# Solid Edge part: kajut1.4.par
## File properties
Author: Mac
Template: Normal.par
Last saved by: Mac
Revision: 16
Application: Solid Edge
Density: 1300,000 kg/m^3
Accuracy: 0,990
Material: Epoxy, cast rigid
Face Style: White
Fill Style: ANSI34(Plastic)
Virtual Style: Shiny resin yellow
Coef. of Thermal Exp: 5.9e-05
Thermal Conductivity: 2.1
Specific Heat: 0.0
Modulus of Elasticity: 3102640650.0
Poission's Ratio: 0.37
Yield Stress: 65500191.5
Ultimate Stress: 0.0
Elongation: 0.0
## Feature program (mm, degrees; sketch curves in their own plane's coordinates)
sketch for "unnamed Protrusion 1" plane through (0, 0, 0) normal (0, 0, 1) x-axis (1, 0, 0)
extrude "unnamed Protrusion 1" add to key point along +normal
replace surface "unnamed ReplaceSurface 1"
sketch for "unnamed Cutout 1" plane through (17.2231, 15.1706, 0) normal (0, 0, -1) x-axis (1, 0, 0)
  line (59.2433, 13.6622) -> (-66.6267, 13.6622)
  line (-66.6267, 50.0572) -> (-66.6267, 13.6622)
  line (-66.6267, 50.0572) -> (59.2433, 50.0572)
  line (59.2433, 50.0572) -> (59.2433, 13.6622)
extrude "unnamed Cutout 1" cut through along -normal
replace surface "unnamed ReplaceSurface 2"
sketch for "unnamed Cutout 2" plane through (16.7161, 1.5084, 17.0568) normal (0, -1, 0) x-axis (1, 0, 0)
  bspline degree 3 poles (9.663, 14.79) (2.5101, 14.9839) (-7.8188, 15.3708) (-21.8608, 14.1482) (-31.0602, 14.1732) (-36.3205, 11.4707) (-51.3807, 10.4837) (-63.2728, 9.3157) (-76.3437, 8.8273) knots 0 0.2257 0.3868 0.4835 0.539 0.5875 1 multiplicities 4 1 1 1 1 1 4
  line (-76.3437, 8.8273) -> (-76.3437, 24.7599)
  line (-76.3437, 24.7599) -> (9.663, 24.7599)
  line (9.663, 24.7599) -> (9.663, 14.79)
extrude "unnamed Cutout 2" cut through along -normal
fillet "Round_3" radius 2
fillet "Round_4" radius 6
fillet "Round_5" radius 2
lofted cutout "unnamed LoftedCutout 1"
sketch for "ExtrudedProtrusion_4" plane through (-14.725, 13.9689, 23.98) normal (0, 0, 1) x-axis (1, 0, 0)
  line (5.4244, -12.4605) -> (-7.7485, -12.4605)
  line (-7.7485, 12.6611) -> (-7.7485, -12.4605)
  line (-7.7485, 12.6611) -> (5.4244, 11.5251)
  line (5.4244, 11.5251) -> (5.4244, -12.4605)
extrude "ExtrudedProtrusion_4" add finite 3 along +normal
sketch for "ExtrudedCutout_6" plane through (0, 31.8282, 0) normal (0, -1, 0) x-axis (1, 0, 0)
  line (50.9356, 3.4307) -> (-32.1242, 3.4307)
  line (50.9356, 3.4307) -> (29.8402, 16.8869)
  line (29.8402, 16.8869) -> (11.2912, 16.8869)
extrude "ExtrudedCutout_6" cut along +normal  Profile_Plane1_Distance = 31.8282 mm
sketch for "unnamed Cutout 3" plane through (65.5056, 0, 0) normal (1, 0, 0) x-axis (0, 1, 0)
  line (1.5043, 3.4307) -> (24.5141, 3.4307)
  line (24.5141, 16.8869) -> (24.5141, 3.4307)
  line (1.5051, 16.8869) -> (24.5141, 16.8869)
  bspline degree 3 poles (1.5043, 3.4307) (1.5046, 7.7872) (1.5048, 12.364) (1.5051, 16.8869) knots 0 1 multiplicities 4 4
extrude "unnamed Cutout 3" cut along +normal
lofted cutout "unnamed LoftedCutout 2"
sketch for "ExtrudedCutout_9" plane through (-32.1251, 15.8889, 13.7207) normal (-1, 0, 0) x-axis (0, -1, 0)
extrude "ExtrudedCutout_9" cut finite 33.2398 along -normal
body pattern "unnamed BodyPattern 1"
pattern "unnamed Pattern 1"
sketch for "unnamed Cutout 4" plane through (-27.2968, 1.5084, 23.78) normal (0, 0, 1) x-axis (0, -1, 0)
  line (0.9627, 19.288) -> (0.9627, 1.6734)
  line (0.9627, 1.6734) -> (4.9627, 1.6734)
  line (4.9627, 19.288) -> (4.9627, 1.6734)
  line (0.9627, 19.288) -> (4.9627, 19.288)
extrude "unnamed Cutout 4" cut along +normal
sketch for "unnamed Protrusion 2" plane through (-8.7893, -12.7105, 25.3849) normal (0.939693, 0, -0.34202) x-axis (0, 1, 0)
  arc centre (1.7521, 7.2455) radius 2 from (3.7521, 7.2455) to (1.7521, 9.2455) ccw
  line (3.7521, 7.2455) -> (3.7521, 1.675)
  line (3.7521, 1.675) -> (-0.2479, 1.675)
  line (-0.2479, 7.2455) -> (-0.2479, 1.675)
  arc centre (1.7521, 7.2455) radius 2 from (-0.2479, 7.2455) to (1.7521, 9.2455) cw
extrude "unnamed Protrusion 2" add through along +normal
sketch for "unnamed Protrusion 3" plane through (-10.8012, 1.5084, 23.98) normal (0, 0, 1) x-axis (1, 0, 0)
  line (11.6904, -14.4667) -> (0.584, -14.4667)
  line (0.584, -10.4667) -> (0.584, -14.4667)
  line (11.6904, -10.4668) -> (0.584, -10.4667)
  line (11.6904, -10.4668) -> (11.6904, -14.4667)
extrude "unnamed Protrusion 3" add along +normal
sketch for "unnamed Protrusion 4" plane through (-15.4114, -13.3019, 27.9786) normal (-0.140003, 0, 0.990151) x-axis (0, -1, 0)
  line (7.1676, -7.1324) -> (10.173, -7.1324)
  bspline degree 3 poles (8.1689, 14.8756) (8.3705, 13.0412) (8.5582, 11.2063) (8.8135, 8.4565) (8.893, 7.5407) (9.0467, 5.7061) (9.1218, 4.787) (9.2739, 2.9584) (9.351, 2.0478) (9.4699, 0.6916) (9.5094, 0.2413) (9.5955, -0.6559) (9.6413, -1.1031) (9.7808, -2.4439) (9.8766, -3.3377) (9.9607, -4.2354) (10.0508, -5.1968) (10.1165, -6.1637) (10.173, -7.1324) knots 0 0.222 0.333 0.444 0.555 0.6105 0.666 0.777 1 multiplicities 4 2 2 2 2 2 2 3 4
  line (-2.1162, 19.1742) -> (-2.1162, 16.0491)
  bspline degree 3 poles (5.3665, 12.8768) (4.9125, 13.1058) (4.4832, 13.3319) (3.6377, 13.7653) (3.2128, 13.9785) (2.3797, 14.374) (1.9605, 14.5622) (1.5389, 14.7404) (0.3553, 15.2407) (-0.8641, 15.6707) (-2.1162, 16.0491) knots 0 0.1546 0.3191 0.4836 1 multiplicities 4 2 2 3 4
  bspline degree 3 poles (7.1676, -7.1324) (7.0849, -5.4182) (6.8925, -3.6731) (6.7039, -1.8603) (6.657, -1.4102) (6.6104, -0.9551) (6.5215, -0.0291) (6.4813, 0.4295) (6.3619, 1.7919) (6.2845, 2.7068) (6.1319, 4.5412) (6.0568, 5.4597) (5.904, 7.2843) (5.8253, 8.1911) (5.6243, 10.3551) (5.499, 11.6154) (5.3665, 12.8768) knots 0 0.316 0.3795 0.443 0.5699 0.6969 0.8238 1 multiplicities 4 3 2 2 2 2 2 4
extrude "unnamed Protrusion 4" add through along -normal
replace surface "unnamed ReplaceSurface 3"
thinwall "Thinwall_5"  Thickness = 0.1 mm
sketch for "ExtrudedCutout_13" plane through (0, 0, 0) normal (0, -1, 0) x-axis (1, 0, 0)
  bspline degree 3 poles (11.2912, 16.2869) (3.5878, 16.3363) (-2.7766, 16.1026) (-8.2178, 15.3761) (-13.0948, 14.7248) (-17.2301, 13.6777) (-20.9403, 12.0868) knots 0 0.381 1 multiplicities 4 3 4
  bspline degree 3 poles (-6.0657, 4.0307) (-9.9941, 6.9536) (-14.9512, 9.6357) (-20.9403, 12.0868) knots 0 1 multiplicities 4 4
  line (48.8793, 4.0307) -> (-6.0657, 4.0307)
  line (48.8793, 4.0307) -> (29.6651, 16.2869)
  line (29.6651, 16.2869) -> (11.2912, 16.2869)
extrude "ExtrudedCutout_13" cut finite 127.1905 symmetric
sketch for "unnamed Cutout 5" #1 plane through (0, 0, 0) normal (1, 0, 0) x-axis (0, 1, 0)
  line (24.0141, 16.3869) -> (24.0141, 4.0307)
  line (24.0141, 4.0307) -> (2.1084, 4.0307)
  line (2.1084, 16.3869) -> (2.1084, 4.0307)
  line (2.1084, 16.3869) -> (24.0141, 16.3869)
sketch for "unnamed Cutout 5" #2 plane through (0, 0, 0) normal (1, 0, 0) x-axis (0, 1, 0)
  line (0.9084, 16.2869) -> (-20.8974, 16.2869)
  line (-20.8974, 16.2869) -> (-20.8974, 4.0307)
  line (-20.8974, 4.0307) -> (0.9084, 4.0307)
  line (0.9084, 16.2869) -> (0.9084, 4.0307)
extrude "unnamed Cutout 5" cut through along +normal
sketch for "unnamed Cutout 6" plane through (-6.9179, -10.9584, 30.5264) normal (-0.939693, 0, 0.34202) x-axis (0, -1, 0)
extrude "unnamed Cutout 6" cut through along -normal
Other named dimensions: "OffsetSurface_1": Distance = 0.08 mm | "OffsetSurface_2": Distance = 0.08 mm | "ExtrudedSurface_1": FiniteDepth = 33.8703 mm | "KeypointCurve_12": EndDerivMagnitude = -6.9482 mm
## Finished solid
Body 1: sheet body, 1 face, 4 edges, 4 vertices.
  Faces by surface: spline 1
  Edges by curve: spline 4
Body 2: sheet body, 5 faces, 28 edges, 24 vertices.
  Faces by surface: offset 3, blend 1, plane 1
  Edges by curve: curve on surface 17, intersection 6, line 4, circle 1
Body 3: sheet body, 1 face, 4 edges, 4 vertices.
  Faces by surface: plane 1
  Edges by curve: line 4
Body 4: sheet body, 1 face, 5 edges, 5 vertices.
  Faces by surface: offset 1
  Edges by curve: curve on surface 5
Body 5: sheet body, 1 face, 5 edges, 5 vertices.
  Faces by surface: offset 1
  Edges by curve: curve on surface 5
Body 6: sheet body, 1 face, 6 edges, 6 vertices.
  Faces by surface: spline 1
  Edges by curve: spline 6
Body 7: solid body, 158 faces, 462 edges, 305 vertices.
  Faces by surface: plane 82, offset 30, blend 16, spline 15, swept 12, cylinder 3
  Edges by curve: intersection 246, line 169, curve on surface 23, circle 16, spline 6, ellipse 2
Body 8: sheet body, 1 face, 4 edges, 4 vertices.
  Faces by surface: spline 1
  Edges by curve: spline 4
Bounding box of the edges (mm; curved faces can reach further): 97.800 x 62.270 x 34.175, from (-32.1319, -27.3865, -0.0609) to (65.6678, 34.883, 34.1136).
Cylindrical faces by radius (mm): R0.75 x1, R1.9 x1, R2 x1
Planar faces by outward normal: +x 5, +y 11, +z 15, -x 5, -y 11, -z 19, oblique 16
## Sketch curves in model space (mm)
spline (-0.0911, -12.9481, 30.1448) -> (-1.1705, -15.655, 29.9922) -> (-2.6614, -18.6684, 29.7814)
spline (-0.8642, -12.9584, 23.98) -> (-1.775, -16.0938, 23.98) -> (-2.8285, -18.7696, 23.98)
line (-32.1251, 29.2689, 15.3989) -> (-32.1251, 34.1731, 15.3989)
line (-32.1251, 34.1731, 15.3989) -> (-32.1251, 34.1731, 31.184)
line (-32.1251, 34.1731, 31.184) -> (-32.1251, -2.4744, 31.184)
line (-32.1251, -2.4744, 31.184) -> (-32.1251, -2.4744, 23.78)
line (-32.1251, -2.4744, 23.78) -> (-32.1251, 1.5084, 23.78)
line (-32.1251, 26.6168, 23.78) -> (-32.1251, 1.5084, 23.78)
line (-32.1251, 26.6168, 23.78) -> (-32.1251, 26.8456, 27.4401)
line (-32.1251, 26.926, 27.4401) -> (-32.1251, 26.8456, 27.4401)
arc centre (-32.1251, 26.926, 25.6295) radius 1.8106 from (-32.1251, 26.926, 27.4401) through (-32.1251, 28.1727, 26.9424) to (-32.1251, 28.7341, 25.7231)
line (-32.1251, 28.7341, 25.7231) -> (-32.1251, 29.2689, 15.3989)
arc centre (-22.4735, 26.4777, 26.3356) radius 1.8156 from (-22.4735, 28.2859, 26.4992) through (-22.4735, 27.6621, 27.7117) to (-22.4735, 26.4777, 28.1512)
line (-22.4735, 26.4777, 28.1512) -> (-22.4735, 26.4401, 28.1512)
spline (-22.4735, 26.4401, 28.1512) -> (-22.4735, 26.3035, 25.9656) -> (-22.4735, 26.1677, 23.78)
line (-22.4735, 26.1677, 23.78) -> (-22.4735, 1.5084, 23.78)
line (-22.4735, -0.6391, 23.78) -> (-22.4735, 1.5084, 23.78)
line (-22.4735, -0.6391, 31.4781) -> (-22.4735, -0.6391, 23.78)
line (-22.4735, 31.672, 31.4781) -> (-22.4735, -0.6391, 31.4781)
line (-22.4735, 31.672, 12.0419) -> (-22.4735, 31.672, 31.4781)
line (-22.4735, 29.4254, 12.0419) -> (-22.4735, 31.672, 12.0419)
spline (-22.4735, 29.4254, 12.0419) -> (-22.4735, 28.895, 19.2736) -> (-22.4735, 28.2859, 26.4992)
line (-22.4735, 34.883, 0) -> (-22.4735, -8.4565, 0)
spline (-6.2658, -47.6819, 3.4307) -> (-28.6201, -47.6819, 14.2849) -> (-63.2786, -47.6819, 22.4937)
spline (11.2912, -47.6819, 16.8869) -> (-8.2966, -47.6819, 15.9707) -> (-22.4691, -47.6819, 12.0543)
line (29.8402, -47.6819, 16.8869) -> (11.2912, -47.6819, 16.8869)
line (-35.7364, -47.6819, 3.4307) -> (-34.3104, -47.6819, 16.0459)
line (50.9356, -47.6819, 3.4307) -> (-35.7364, -47.6819, 3.4307)
line (50.9356, -47.6819, 3.4307) -> (29.8402, -47.6819, 16.8869)
line (-32.1251, 26.4289, 23.98) -> (-32.1251, 1.5084, 23.98)
line (0.8634, 1.5084, 23.98) -> (-32.1251, 1.5084, 23.98)
spline (-4.3006, 24.3165, 23.98) -> (-0.6205, 14.9508, 23.98) -> (0.8634, 1.5084, 23.98)
spline (-4.3006, 24.3165, 23.98) -> (-22.4089, 25.9758, 23.98) -> (-32.1251, 26.4289, 23.98)
line (5.6852, 1.5084, 31.9844) -> (-32.1251, 1.5084, 31.9844)
spline (5.6852, 1.5084, 31.9844) -> (2.287, 17.6314, 31.9844) -> (-0.9003, 24.4875, 31.9844)
spline (-0.9003, 24.4875, 31.9844) -> (-11.7068, 25.4973, 31.9844) -> (-32.1251, 26.9293, 31.9844)
line (-32.1251, 26.9293, 31.9844) -> (-32.1251, 1.5084, 31.9844)
line (-59.6276, 1.5084, 25.8841) -> (-59.6276, 1.5084, 41.8168)
line (-59.6276, 1.5084, 41.8168) -> (26.3791, 1.5084, 41.8168)
line (26.3791, 1.5084, 41.8168) -> (26.3791, 1.5084, 31.8468)
spline (26.3791, 1.5084, 31.8468) -> (-16.7027, 1.5084, 29.9221) -> (-59.6276, 1.5084, 25.8841)
spline (-7.395, 25.9435, 34.1136) -> (-19.2834, 27.357, 34.1136) -> (-32.1251, 28.4997, 34.1136)
spline (0.7256, 0, 34.1136) -> (-1.5887, 13.3712, 34.1136) -> (-7.395, 25.9435, 34.1136)
spline (65.6678, 0, 0) -> (40.22, 0, 17.3758) -> (0.7256, 0, 34.1136)
line (-32.1251, 0, 0) -> (65.6678, 0, 0)
spline (65.6678, 0, 0) -> (63.3536, 13.3712, 0) -> (57.5472, 25.9435, 0)
spline (57.5472, 25.9435, 0) -> (34.8062, 28.3456, 0) -> (8.6507, 29.8164, 0)
spline (8.6507, 29.8164, 0) -> (-10.9903, 30.2656, 0) -> (-32.1251, 30.2669, 0)
line (-32.1251, 30.2669, 0) -> (-32.1251, 0, 0)
spline (57.5472, 25.9435, 0) -> (32.0994, 25.9435, 17.3758) -> (-7.395, 25.9435, 34.1136)
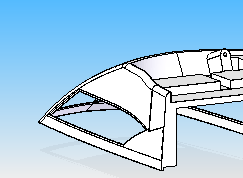
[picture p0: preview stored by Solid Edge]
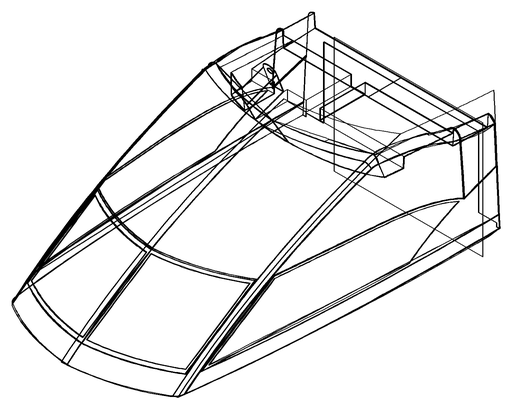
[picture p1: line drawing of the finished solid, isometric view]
